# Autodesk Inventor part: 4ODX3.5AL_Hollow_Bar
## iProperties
Shininess: 64.0
Length Units: 11272
Angle Units: 11279
Time Units: 11290
Mass Units: 11286
Length Display Precision: 3
Angle Display Precision: 2
Compacted: True
Part Number: 4ODX3.5AL_Hollow_Bar
Document SubType Name: Modeling
Created: 2004-08
Designer: John Blackburn
Manufacturer: Standard
Standards Organization: Custom
Material: Aluminum-6061
Density: 0.0
Volumn: 0.0
Area: 0.0
PropertySet Name: Model Information
Control State: 0
Master: False
Checked Out: False
Author: John Blackburn
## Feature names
1. Extrusion1
2. Extrusion2
3. Hole1
4. Extrusion3
5. Hole2
